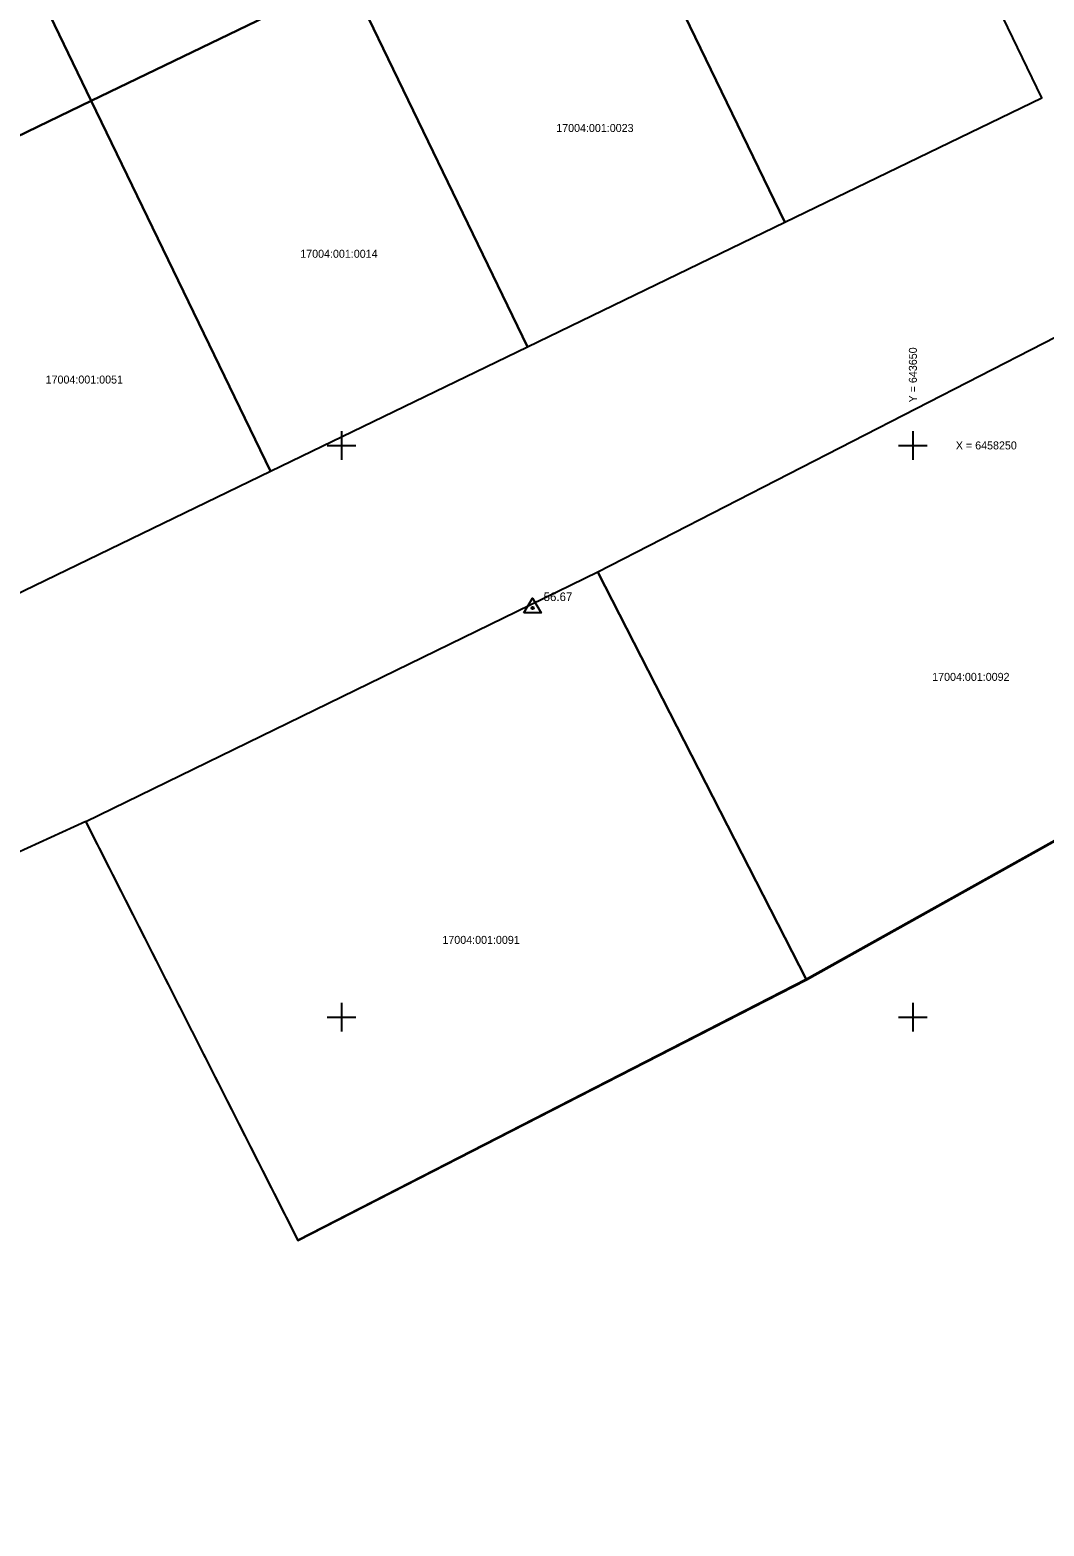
# Model space of a CAD drawing. Extents: x 643307 to 644029, y 6457938 to 6458417.
# Drawn here: x 643572.7 to 643661.5, y 6458155.5 to 6458286.3 of the extents above; entities that cross this region are included whole.
import ezdxf

# ---------------------------------------------------------------- set-up
doc = ezdxf.new("R2010")
doc.units = 0
for name, color, linetype in [('30_TEE', 7, 'Continuous'), ('40_PIIR', 7, 'Continuous'), ('59_KORGUS', 7, 'Continuous'), ('60_ALUSVORK', 7, 'Continuous'), ('62_MOOTMPUNKT', 7, 'Continuous'), ('63_VORK', 7, 'Continuous'), ('Level 55', 7, 'Continuous')]:
    doc.layers.add(name, color=color, linetype=linetype)

# ---------------------------------------------------------------- blocks, each defined once
blk = doc.blocks.new('RING02')
at = {"layer": '59_KORGUS'}
blk.add_circle((0, 0), 0.2, dxfattribs=at)
blk = doc.blocks.new('RIIKVP')
at = {"layer": '60_ALUSVORK'}
blk.add_lwpolyline([(-1.5, -0.87), (0, 1.73), (1.5, -0.87)], close=True, dxfattribs=at)
blk.add_circle((0, 0), 0.2, dxfattribs=at)
blk = doc.blocks.new('VKORIS')
at = {"layer": '30_TEE'}
for p, q in [((-2.5, 0), (2.5, 0)), ((0, 2.5), (0, -2.5))]:
    blk.add_line(p, q, dxfattribs=at)

msp = doc.modelspace()

# ---------------------------------------------------------------- linework, layer by layer
at = {"layer": '40_PIIR'}
for points in [[(643584.92, 6458323.42), (643562.42, 6458312.54), (643578.1, 6458280.14), (643600.6, 6458291.02)], [(643638.79, 6458269.51), (643661.29, 6458280.4), (643645.61, 6458312.8), (643623.11, 6458301.91)], [(643562.42, 6458312.54), (643539.91, 6458301.65), (643555.6, 6458269.25), (643578.1, 6458280.14)], [(643616.29, 6458258.63), (643638.79, 6458269.51), (643623.11, 6458301.91), (643600.6, 6458291.02)], [(643593.78, 6458247.74), (643616.29, 6458258.63), (643600.6, 6458291.02), (643578.1, 6458280.14)], [(643571.28, 6458236.85), (643593.78, 6458247.74), (643578.1, 6458280.14), (643555.6, 6458269.25)], [(643667.01, 6458261.77), (643622.44, 6458238.91), (643640.69, 6458203.28), (643682.09, 6458226.39)], [(643622.44, 6458238.91), (643577.62, 6458217.08), (643596.19, 6458180.47), (643640.69, 6458203.28)]]:
    msp.add_lwpolyline(points, close=True, dxfattribs=at)
msp.add_lwpolyline([(643682.1, 6458226.44), (643640.7, 6458203.32), (643596.21, 6458180.5), (643577.63, 6458217.12), (643524.52, 6458192.86), (643470.91, 6458180.25), (643307.72, 6458113.06), (643332.91, 6458059.18), (643306.72, 6457954.23), (643320.92, 6457937.78), (643400.22, 6458002.65), (643406.53, 6458008.17), (643425.42, 6458018.14), (643460.11, 6458026.65), (643485.04, 6458027.42), (643512.63, 6458065.31), (643522.44, 6458075.5), (643561.79, 6458082.2), (643607.16, 6458094.29), (643635.9, 6458099.65), (643671.27, 6458113.67)], dxfattribs=at)
at = {"layer": 'Level 55'}
msp.add_line((643616.72, 6458235.79), (643616.72, 6458235.79), dxfattribs=at)

# ---------------------------------------------------------------- block references
at = {"layer": '60_ALUSVORK', "xscale": 0.5, "yscale": 0.5}
msp.add_blockref('RIIKVP', (643616.72, 6458235.79), dxfattribs=at)
at = {"layer": '62_MOOTMPUNKT', "xscale": 0.5, "yscale": 0.5}
msp.add_blockref('RING02', (643616.72, 6458235.79), dxfattribs=at)
at = {"layer": '63_VORK', "xscale": 0.5, "yscale": 0.5}
for p in [(643600, 6458250), (643650, 6458250), (643600, 6458200), (643650, 6458200)]:
    msp.add_blockref('VKORIS', p, dxfattribs=at)

# ---------------------------------------------------------------- texts
at = {"layer": '40_PIIR'}
for s, p in [('17004:001:0023', (643618.79, 6458277.41)), ('17004:001:0014', (643596.39, 6458266.41)), ('17004:001:0051', (643574.11, 6458255.41)), ('17004:001:0092', (643651.69, 6458229.41)), ('17004:001:0091', (643608.83, 6458206.41))]:
    msp.add_text(s, height=0.7, dxfattribs=at).set_placement(p)
at = {"layer": '59_KORGUS'}
msp.add_text('56.67', height=0.75, dxfattribs=at).set_placement((643617.69, 6458236.39))
at = {"layer": '63_VORK'}
msp.add_text(' Y = 643650', height=0.7, rotation=90, dxfattribs=at).set_placement((643650.35, 6458253.5))
msp.add_text(' X = 6458250', height=0.7, dxfattribs=at).set_placement((643653.5, 6458249.65))

doc.saveas('drawing.dxf')
